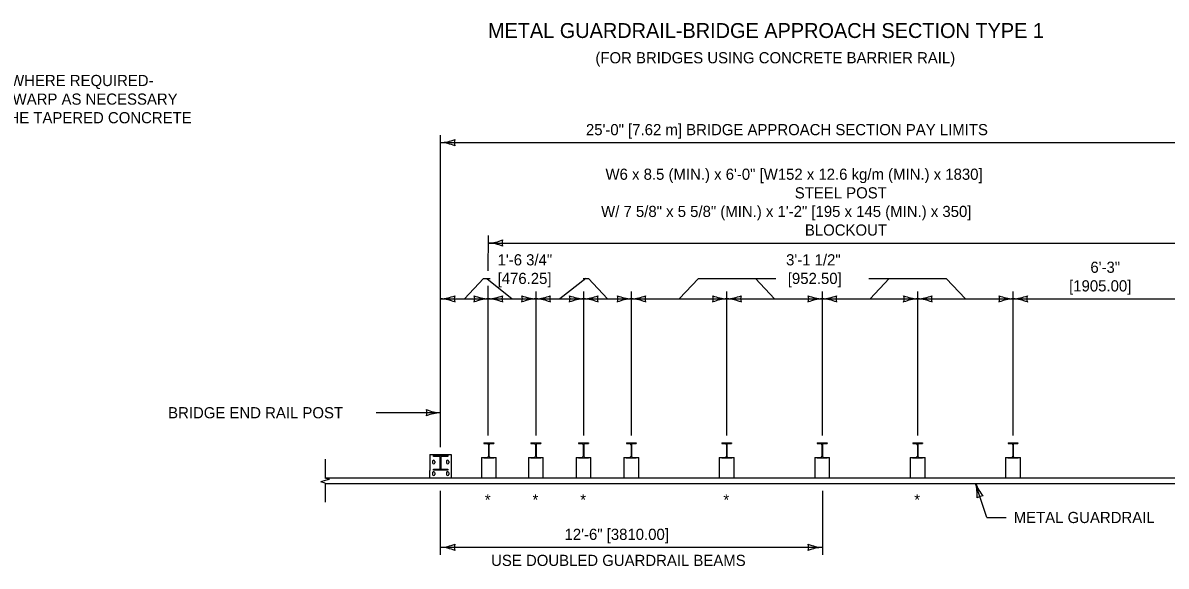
# Model space of a CAD drawing. Extents: x 49991.4 to 50021, y 49987.6 to 50011.4.
# Drawn here: x 50007.52 to 50013.67, y 49992.8 to 49995.72 of the extents above; entities that cross this region are included whole.
import ezdxf

# ---------------------------------------------------------------- set-up
doc = ezdxf.new("R2010")
doc.units = 0
for name, color, linetype in [('Level 1', 7, 'Continuous'), ('Level 2', 7, 'Continuous'), ('Level 3', 7, 'Continuous'), ('Level 6', 7, 'Continuous')]:
    doc.layers.add(name, color=color, linetype=linetype)

msp = doc.modelspace()

# ---------------------------------------------------------------- linework, layer by layer
at = {"layer": 'Level 1'}
for p, q in [((50010.0017, 49993.4645), (50010.0542, 49993.4645)), ((50010.0017, 49993.4645), (50010.0017, 49993.4616)), ((50010.0017, 49993.4616), (50010.0197, 49993.4616)), ((50010.0362, 49993.4616), (50010.0542, 49993.4616)), ((50010.0542, 49993.4645), (50010.0542, 49993.4616)), ((50010.2546, 49993.4645), (50010.3071, 49993.4645)), ((50010.2546, 49993.4645), (50010.2546, 49993.4616)), ((50010.2546, 49993.4616), (50010.2726, 49993.4616)), ((50010.2891, 49993.4616), (50010.3071, 49993.4616)), ((50010.3071, 49993.4645), (50010.3071, 49993.4616)), ((50010.5112, 49993.4645), (50010.5637, 49993.4645)), ((50010.5112, 49993.4645), (50010.5112, 49993.4616)), ((50010.5112, 49993.4616), (50010.5292, 49993.4616)), ((50010.5457, 49993.4616), (50010.5637, 49993.4616)), ((50010.5637, 49993.4645), (50010.5637, 49993.4616)), ((50010.7678, 49993.4645), (50010.8203, 49993.4645)), ((50010.7678, 49993.4645), (50010.7678, 49993.4616)), ((50010.7678, 49993.4616), (50010.7858, 49993.4616)), ((50010.8023, 49993.4616), (50010.8203, 49993.4616)), ((50010.8203, 49993.4645), (50010.8203, 49993.4616)), ((50011.281, 49993.4645), (50011.3335, 49993.4645)), ((50011.281, 49993.4645), (50011.281, 49993.4616)), ((50011.281, 49993.4616), (50011.299, 49993.4616)), ((50011.3155, 49993.4616), (50011.3335, 49993.4616)), ((50011.3335, 49993.4645), (50011.3335, 49993.4616)), ((50011.7942, 49993.4645), (50011.8467, 49993.4645)), ((50011.7942, 49993.4645), (50011.7942, 49993.4616)), ((50011.7942, 49993.4616), (50011.8122, 49993.4616)), ((50011.8287, 49993.4616), (50011.8467, 49993.4616)), ((50011.8467, 49993.4645), (50011.8467, 49993.4616)), ((50012.3074, 49993.4645), (50012.3599, 49993.4645)), ((50012.3074, 49993.4645), (50012.3074, 49993.4616)), ((50012.3074, 49993.4616), (50012.3254, 49993.4616)), ((50012.3419, 49993.4616), (50012.3599, 49993.4616)), ((50012.3599, 49993.4645), (50012.3599, 49993.4616)), ((50012.8206, 49993.4645), (50012.8731, 49993.4645)), ((50012.8206, 49993.4645), (50012.8206, 49993.4616)), ((50012.8206, 49993.4616), (50012.8386, 49993.4616)), ((50012.8551, 49993.4616), (50012.8731, 49993.4616)), ((50012.8731, 49993.4645), (50012.8731, 49993.4616)), ((50009.7114, 49993.402), (50009.8264, 49993.402)), ((50009.7114, 49993.402), (50009.7114, 49993.3163)), ((50009.8264, 49993.402), (50009.8264, 49993.3163)), ((50010.0268, 49993.4545), (50010.0268, 49993.3944)), ((50010.0291, 49993.4545), (50010.0291, 49993.3944)), ((50010.2797, 49993.4545), (50010.2797, 49993.3944)), ((50010.282, 49993.4545), (50010.282, 49993.3944)), ((50010.5363, 49993.4545), (50010.5363, 49993.3944)), ((50010.5386, 49993.4545), (50010.5386, 49993.3944)), ((50010.7929, 49993.4545), (50010.7929, 49993.3944)), ((50010.7952, 49993.4545), (50010.7952, 49993.3944)), ((50011.3061, 49993.4545), (50011.3061, 49993.3944)), ((50011.3084, 49993.4545), (50011.3084, 49993.3944)), ((50011.8193, 49993.4545), (50011.8193, 49993.3944)), ((50011.8216, 49993.4545), (50011.8216, 49993.3944)), ((50012.3325, 49993.4545), (50012.3325, 49993.3944)), ((50012.3348, 49993.4545), (50012.3348, 49993.3944)), ((50012.8457, 49993.4545), (50012.8457, 49993.3944)), ((50012.848, 49993.4545), (50012.848, 49993.3944)), ((50009.7249, 49993.3657), (50009.7249, 49993.3584)), ((50009.7307, 49993.397), (50009.8071, 49993.397)), ((50009.7307, 49993.3924), (50009.7307, 49993.397)), ((50009.7623, 49993.3924), (50009.7307, 49993.3924)), ((50009.7376, 49993.3657), (50009.7376, 49993.3584)), ((50009.7672, 49993.3281), (50009.7672, 49993.3875)), ((50009.7705, 49993.3875), (50009.7705, 49993.3281)), ((50009.8071, 49993.3924), (50009.7754, 49993.3924)), ((50009.8, 49993.3657), (50009.8, 49993.3584)), ((50009.8071, 49993.397), (50009.8071, 49993.3924)), ((50009.8128, 49993.3657), (50009.8128, 49993.3584)), ((50009.9879, 49993.3873), (50009.9879, 49993.277)), ((50009.9879, 49993.3873), (50010.001, 49993.3873)), ((50010.001, 49993.3844), (50010.001, 49993.3873)), ((50010.001, 49993.3844), (50010.0549, 49993.3844)), ((50010.0017, 49993.3844), (50010.0017, 49993.3873)), ((50010.0017, 49993.3873), (50010.0197, 49993.3873)), ((50010.0362, 49993.3873), (50010.0542, 49993.3873)), ((50010.0542, 49993.3844), (50010.0542, 49993.3873)), ((50010.0549, 49993.3844), (50010.0549, 49993.3873)), ((50010.0549, 49993.3873), (50010.068, 49993.3873)), ((50010.068, 49993.277), (50010.068, 49993.3873)), ((50010.2408, 49993.3873), (50010.2408, 49993.277)), ((50010.2408, 49993.3873), (50010.2539, 49993.3873)), ((50010.2539, 49993.3844), (50010.2539, 49993.3873)), ((50010.2539, 49993.3844), (50010.3078, 49993.3844)), ((50010.2546, 49993.3844), (50010.2546, 49993.3873)), ((50010.2546, 49993.3873), (50010.2726, 49993.3873)), ((50010.2891, 49993.3873), (50010.3071, 49993.3873)), ((50010.3071, 49993.3844), (50010.3071, 49993.3873)), ((50010.3078, 49993.3844), (50010.3078, 49993.3873)), ((50010.3078, 49993.3873), (50010.3209, 49993.3873)), ((50010.3209, 49993.277), (50010.3209, 49993.3873)), ((50010.4974, 49993.3873), (50010.4974, 49993.277)), ((50010.4974, 49993.3873), (50010.5105, 49993.3873)), ((50010.5105, 49993.3844), (50010.5105, 49993.3873)), ((50010.5105, 49993.3844), (50010.5644, 49993.3844)), ((50010.5112, 49993.3844), (50010.5112, 49993.3873)), ((50010.5112, 49993.3873), (50010.5292, 49993.3873)), ((50010.5457, 49993.3873), (50010.5637, 49993.3873)), ((50010.5637, 49993.3844), (50010.5637, 49993.3873)), ((50010.5644, 49993.3844), (50010.5644, 49993.3873)), ((50010.5644, 49993.3873), (50010.5775, 49993.3873)), ((50010.5775, 49993.277), (50010.5775, 49993.3873)), ((50010.754, 49993.3873), (50010.754, 49993.277)), ((50010.754, 49993.3873), (50010.7671, 49993.3873)), ((50010.7671, 49993.3844), (50010.7671, 49993.3873)), ((50010.7671, 49993.3844), (50010.821, 49993.3844)), ((50010.7678, 49993.3844), (50010.7678, 49993.3873)), ((50010.7678, 49993.3873), (50010.7858, 49993.3873)), ((50010.8023, 49993.3873), (50010.8203, 49993.3873)), ((50010.8203, 49993.3844), (50010.8203, 49993.3873)), ((50010.821, 49993.3844), (50010.821, 49993.3873)), ((50010.821, 49993.3873), (50010.8341, 49993.3873)), ((50010.8341, 49993.277), (50010.8341, 49993.3873)), ((50011.2672, 49993.3873), (50011.2672, 49993.277)), ((50011.2672, 49993.3873), (50011.2803, 49993.3873)), ((50011.2803, 49993.3844), (50011.2803, 49993.3873)), ((50011.2803, 49993.3844), (50011.3342, 49993.3844)), ((50011.281, 49993.3844), (50011.281, 49993.3873)), ((50011.281, 49993.3873), (50011.299, 49993.3873)), ((50011.3155, 49993.3873), (50011.3335, 49993.3873)), ((50011.3335, 49993.3844), (50011.3335, 49993.3873)), ((50011.3342, 49993.3844), (50011.3342, 49993.3873)), ((50011.3342, 49993.3873), (50011.3473, 49993.3873)), ((50011.3473, 49993.277), (50011.3473, 49993.3873)), ((50011.7804, 49993.3873), (50011.7804, 49993.277)), ((50011.7804, 49993.3873), (50011.7935, 49993.3873)), ((50011.7935, 49993.3844), (50011.7935, 49993.3873)), ((50011.7935, 49993.3844), (50011.8474, 49993.3844)), ((50011.7942, 49993.3844), (50011.7942, 49993.3873)), ((50011.7942, 49993.3873), (50011.8122, 49993.3873)), ((50011.8287, 49993.3873), (50011.8467, 49993.3873)), ((50011.8467, 49993.3844), (50011.8467, 49993.3873)), ((50011.8474, 49993.3844), (50011.8474, 49993.3873)), ((50011.8474, 49993.3873), (50011.8605, 49993.3873)), ((50011.8605, 49993.277), (50011.8605, 49993.3873)), ((50012.2936, 49993.3873), (50012.2936, 49993.277)), ((50012.2936, 49993.3873), (50012.3067, 49993.3873)), ((50012.3067, 49993.3844), (50012.3067, 49993.3873)), ((50012.3067, 49993.3844), (50012.3606, 49993.3844)), ((50012.3074, 49993.3844), (50012.3074, 49993.3873)), ((50012.3074, 49993.3873), (50012.3254, 49993.3873)), ((50012.3419, 49993.3873), (50012.3599, 49993.3873)), ((50012.3599, 49993.3844), (50012.3599, 49993.3873)), ((50012.3606, 49993.3844), (50012.3606, 49993.3873)), ((50012.3606, 49993.3873), (50012.3737, 49993.3873)), ((50012.3737, 49993.277), (50012.3737, 49993.3873)), ((50012.8068, 49993.3873), (50012.8068, 49993.277)), ((50012.8068, 49993.3873), (50012.8199, 49993.3873)), ((50012.8199, 49993.3844), (50012.8199, 49993.3873)), ((50012.8199, 49993.3844), (50012.8738, 49993.3844)), ((50012.8206, 49993.3844), (50012.8206, 49993.3873)), ((50012.8206, 49993.3873), (50012.8386, 49993.3873)), ((50012.8551, 49993.3873), (50012.8731, 49993.3873)), ((50012.8731, 49993.3844), (50012.8731, 49993.3873)), ((50012.8738, 49993.3844), (50012.8738, 49993.3873)), ((50012.8738, 49993.3873), (50012.8869, 49993.3873)), ((50012.8869, 49993.277), (50012.8869, 49993.3873)), ((50009.1482, 49993.277), (50014.1642, 49993.277)), ((50009.7114, 49993.277), (50009.7114, 49993.3163)), ((50009.7114, 49993.277), (50009.8264, 49993.277)), ((50009.7249, 49993.3032), (50009.7249, 49993.2959)), ((50009.7308, 49993.3183), (50009.7308, 49993.3229)), ((50009.7308, 49993.3229), (50009.7624, 49993.3229)), ((50009.8072, 49993.3183), (50009.7308, 49993.3183)), ((50009.7376, 49993.3032), (50009.7376, 49993.2959)), ((50009.7754, 49993.3229), (50009.8072, 49993.3229)), ((50009.7999, 49993.3032), (50009.7999, 49993.2959)), ((50009.8072, 49993.3229), (50009.8072, 49993.3183)), ((50009.8126, 49993.3032), (50009.8126, 49993.2959)), ((50009.8264, 49993.3163), (50009.8264, 49993.277)), ((50009.1482, 49993.247), (50014.1642, 49993.247))]:
    msp.add_line(p, q, dxfattribs=at)
for centre, radius, start, end in [((50010.0197, 49993.4545), 0.00714, 0, 90), ((50010.0362, 49993.4545), 0.00714, 90, 180), ((50010.2726, 49993.4545), 0.00714, 0, 90), ((50010.2891, 49993.4545), 0.00714, 90, 180), ((50010.5292, 49993.4545), 0.00714, 0, 90), ((50010.5457, 49993.4545), 0.00714, 90, 180), ((50010.7858, 49993.4545), 0.00714, 0, 90), ((50010.8023, 49993.4545), 0.00714, 90, 180), ((50011.299, 49993.4545), 0.00714, 0, 90), ((50011.3155, 49993.4545), 0.00714, 90, 180), ((50011.8122, 49993.4545), 0.00714, 0, 90), ((50011.8287, 49993.4545), 0.00714, 90, 180), ((50012.3254, 49993.4545), 0.00714, 0, 90), ((50012.3419, 49993.4545), 0.00714, 90, 180), ((50012.8386, 49993.4545), 0.00714, 0, 90), ((50012.8551, 49993.4545), 0.00714, 90, 180), ((50009.7313, 49993.3657), 0.00635, 359.99369, 180.03756), ((50009.7313, 49993.3584), 0.00635, 180.00006, 359.9937), ((50009.7623, 49993.3875), 0.00489, 0, 90), ((50009.7754, 49993.3875), 0.00489, 90, 180), ((50009.8063, 49993.3657), 0.00635, 359.99369, 180.03756), ((50009.8063, 49993.3584), 0.00635, 180.00006, 359.9937), ((50010.0197, 49993.3944), 0.00714, 270, 0), ((50010.0362, 49993.3944), 0.00714, 180, 270), ((50010.2726, 49993.3944), 0.00714, 270, 0), ((50010.2891, 49993.3944), 0.00714, 180, 270), ((50010.5292, 49993.3944), 0.00714, 270, 0), ((50010.5457, 49993.3944), 0.00714, 180, 270), ((50010.7858, 49993.3944), 0.00714, 270, 0), ((50010.8023, 49993.3944), 0.00714, 180, 270), ((50011.299, 49993.3944), 0.00714, 270, 0), ((50011.3155, 49993.3944), 0.00714, 180, 270), ((50011.8122, 49993.3944), 0.00714, 270, 0), ((50011.8287, 49993.3944), 0.00714, 180, 270), ((50012.3254, 49993.3944), 0.00714, 270, 0), ((50012.3419, 49993.3944), 0.00714, 180, 270), ((50012.8386, 49993.3944), 0.00714, 270, 0), ((50012.8551, 49993.3944), 0.00714, 180, 270), ((50009.7313, 49993.3032), 0.00635, 359.99369, 180.03756), ((50009.7313, 49993.2959), 0.00635, 180.00006, 359.9937), ((50009.7627, 49993.3274), 0.00455, 266.76442, 8.43425), ((50009.7755, 49993.3279), 0.00499, 177.45438, 269.51567), ((50009.8063, 49993.3032), 0.00635, 359.99369, 180.03756), ((50009.8063, 49993.2959), 0.00635, 180.00006, 359.9937)]:
    msp.add_arc(centre, radius, start, end, dxfattribs=at)
at = {"layer": 'Level 3'}
for p, q in [((50009.7689, 49993.442), (50009.7689, 49995.1188)), ((50009.7689, 49995.0788), (50014.8318, 49995.0788)), ((50010.0255, 49994.3891), (50010.0257, 49994.5791)), ((50010.0257, 49994.5391), (50013.8745, 49994.5391)), ((50010, 49994.3491), (50009.8966, 49994.2391)), ((50010, 49994.3491), (50010.0354, 49994.3491)), ((50010.0177, 49994.3491), (50010.1532, 49994.2391)), ((50010.5493, 49994.3491), (50010.4104, 49994.2391)), ((50010.535, 49994.3491), (50010.5636, 49994.3491)), ((50010.5636, 49994.3491), (50010.667, 49994.2391)), ((50011.1553, 49994.3491), (50011.0519, 49994.2391)), ((50011.1553, 49994.3491), (50011.5721, 49994.3491)), ((50011.4617, 49994.3491), (50011.5651, 49994.2391)), ((50012.0716, 49994.3491), (50012.4881, 49994.3491)), ((50012.1817, 49994.3491), (50012.0783, 49994.2391)), ((50012.4881, 49994.3491), (50012.5915, 49994.2391)), ((50010.0255, 49993.5045), (50010.0255, 49994.3091)), ((50010.2821, 49993.5045), (50010.2821, 49994.2791)), ((50010.5387, 49993.5045), (50010.5387, 49994.2791)), ((50010.7953, 49993.5045), (50010.7953, 49994.2791)), ((50011.3085, 49993.5045), (50011.3085, 49994.2791)), ((50011.8217, 49993.5045), (50011.8217, 49994.2791)), ((50012.3349, 49993.5045), (50012.3349, 49994.2791)), ((50012.8481, 49993.5045), (50012.8481, 49994.2791)), ((50009.7689, 49994.2391), (50013.8745, 49994.2391)), ((50009.7689, 49993.6271), (50009.4231, 49993.6271)), ((50012.7056, 49993.0641), (50012.6461, 49993.247)), ((50009.7689, 49992.8635), (50009.7689, 49993.207)), ((50011.8219, 49993.207), (50011.8219, 49992.8635)), ((50012.7056, 49993.0641), (50012.8107, 49993.0641)), ((50011.8219, 49992.9035), (50009.7689, 49992.9035))]:
    msp.add_line(p, q, dxfattribs=at)
for centre, radius, start, end in [((50009.7574, 49995.3115), 0.233, 272.82731, 292.07716), ((50009.7598, 49994.8566), 0.2223, 67.45601, 87.63952), ((50009.8971, 49995.0788), 0.0548, 162.13882, 197.86118), ((50010.0142, 49994.7718), 0.233, 272.82731, 292.07716), ((50010.0165, 49994.317), 0.2223, 67.45601, 87.63952), ((50010.1539, 49994.5391), 0.0548, 162.13882, 197.86118), ((50009.7574, 49994.4718), 0.233, 272.82731, 292.07716), ((50009.7598, 49994.017), 0.2223, 67.45601, 87.63952), ((50009.8971, 49994.2391), 0.0548, 162.13882, 197.86118), ((50010.0347, 49994.4612), 0.2223, 247.45601, 267.63952), ((50009.8973, 49994.2391), 0.0548, 342.13882, 17.86118), ((50010.037, 49994.0064), 0.233, 92.82731, 112.07716), ((50010.014, 49994.4718), 0.233, 272.82731, 292.07716), ((50010.0164, 49994.017), 0.2223, 67.45601, 87.63952), ((50010.1537, 49994.2391), 0.0548, 162.13882, 197.86118), ((50010.2913, 49994.4612), 0.2223, 247.45601, 267.63952), ((50010.1539, 49994.2391), 0.0548, 342.13882, 17.86118), ((50010.2936, 49994.0064), 0.233, 92.82731, 112.07716), ((50010.2706, 49994.4718), 0.233, 272.82731, 292.07716), ((50010.273, 49994.017), 0.2223, 67.45601, 87.63952), ((50010.4103, 49994.2391), 0.0548, 162.13882, 197.86118), ((50010.5479, 49994.4612), 0.2223, 247.45601, 267.63952), ((50010.4105, 49994.2391), 0.0548, 342.13882, 17.86118), ((50010.5502, 49994.0064), 0.233, 92.82731, 112.07716), ((50010.5272, 49994.4718), 0.233, 272.82731, 292.07716), ((50010.5296, 49994.017), 0.2223, 67.45601, 87.63952), ((50010.6669, 49994.2391), 0.0548, 162.13882, 197.86118), ((50010.8045, 49994.4612), 0.2223, 247.45601, 267.63952), ((50010.6671, 49994.2391), 0.0548, 342.13882, 17.86118), ((50010.8068, 49994.0064), 0.233, 92.82731, 112.07716), ((50010.7838, 49994.4718), 0.233, 272.82731, 292.07716), ((50010.7862, 49994.017), 0.2223, 67.45601, 87.63952), ((50010.9235, 49994.2391), 0.0548, 162.13882, 197.86118), ((50011.3177, 49994.4612), 0.2223, 247.45601, 267.63952), ((50011.1803, 49994.2391), 0.0548, 342.13882, 17.86118), ((50011.32, 49994.0064), 0.233, 92.82731, 112.07716), ((50011.297, 49994.4718), 0.233, 272.82731, 292.07716), ((50011.2994, 49994.017), 0.2223, 67.45601, 87.63952), ((50011.4367, 49994.2391), 0.0548, 162.13882, 197.86118), ((50011.8309, 49994.4612), 0.2223, 247.45601, 267.63952), ((50011.6935, 49994.2391), 0.0548, 342.13882, 17.86118), ((50011.8332, 49994.0064), 0.233, 92.82731, 112.07716), ((50011.8102, 49994.4718), 0.233, 272.82731, 292.07716), ((50011.8126, 49994.017), 0.2223, 67.45601, 87.63952), ((50011.9499, 49994.2391), 0.0548, 162.13882, 197.86118), ((50012.3441, 49994.4612), 0.2223, 247.45601, 267.63952), ((50012.2067, 49994.2391), 0.0548, 342.13882, 17.86118), ((50012.3464, 49994.0064), 0.233, 92.82731, 112.07716), ((50012.3234, 49994.4718), 0.233, 272.82731, 292.07716), ((50012.3258, 49994.017), 0.2223, 67.45601, 87.63952), ((50012.4631, 49994.2391), 0.0548, 162.13882, 197.86118), ((50012.8573, 49994.4612), 0.2223, 247.45601, 267.63952), ((50012.7199, 49994.2391), 0.0548, 342.13882, 17.86118), ((50012.8596, 49994.0064), 0.233, 92.82731, 112.07716), ((50012.8366, 49994.4718), 0.233, 272.82731, 292.07716), ((50012.839, 49994.017), 0.2223, 67.45601, 87.63952), ((50012.9763, 49994.2391), 0.0548, 162.13882, 197.86118), ((50009.7781, 49993.8492), 0.2223, 247.45601, 267.63952), ((50009.6407, 49993.6271), 0.0548, 342.13882, 17.86118), ((50009.7804, 49993.3944), 0.233, 92.82731, 112.07716), ((50012.432, 49993.187), 0.2223, 355.47646, 15.65997), ((50012.8639, 49993.3299), 0.233, 200.84776, 220.09761), ((50012.6858, 49993.1251), 0.0548, 90.15927, 125.88163), ((50009.7574, 49993.1362), 0.233, 272.82731, 292.07716), ((50009.8971, 49992.9035), 0.0548, 162.13882, 197.86118), ((50011.8311, 49993.1256), 0.2223, 247.45601, 267.63952), ((50011.6937, 49992.9035), 0.0548, 342.13882, 17.86118), ((50009.7598, 49992.6814), 0.2223, 67.45601, 87.63952), ((50011.8334, 49992.6708), 0.233, 92.82731, 112.07716)]:
    msp.add_arc(centre, radius, start, end, dxfattribs=at)
at = {"layer": 'Level 6'}
for p, q in [((50009.1482, 49993.377), (50009.1482, 49993.275)), ((50009.1482, 49993.2621), (50009.1253, 49993.2556)), ((50009.1482, 49993.2492), (50009.1253, 49993.2556)), ((50009.1711, 49993.2686), (50009.1482, 49993.275)), ((50009.1711, 49993.2686), (50009.1482, 49993.2621)), ((50009.1482, 49993.2492), (50009.1482, 49993.147))]:
    msp.add_line(p, q, dxfattribs=at)

# ---------------------------------------------------------------- texts
at = {"layer": 'Level 2'}
for s, height, p in [('METAL GUARDRAIL-BRIDGE APPROACH SECTION TYPE 1', 0.08, (50010.0234, 49995.6414)), ('(FOR BRIDGES USING CONCRETE BARRIER RAIL)', 0.06, (50010.6013, 49995.5052)), ('STD. CONC. CURB (WHERE REQUIRED-', 0.06, (50006.6917, 49995.3829)), ('SEE ROAD PLANS) (WARP AS NECESSARY', 0.06, (50006.6917, 49995.2829)), ('TO MEET END OF THE TAPERED CONCRETE ', 0.06, (50006.6917, 49995.1829)), ('25\'-0" [7.62 m] BRIDGE APPROACH SECTION PAY LIMITS', 0.06, (50010.5504, 49995.1188)), ('W6 x 8.5 (MIN.) x 6\'-0" [W152 x 12.6 kg/m (MIN.) x 1830]', 0.06, (50010.6556, 49994.8791)), ('STEEL POST', 0.06, (50011.6734, 49994.7791)), ('W/ 7 5/8" x 5 5/8" (MIN.) x 1\'-2" [195 x 145 (MIN.) x 350]', 0.06, (50010.632, 49994.6791)), ('BLOCKOUT', 0.06, (50011.7278, 49994.5791)), ('1\'-6 3/4"', 0.06, (50010.0754, 49994.4191)), ('3\'-1 1/2"', 0.06, (50011.6266, 49994.4191)), ('6\'-3"', 0.06, (50013.263, 49994.3791)), ('[476.25]', 0.06, (50010.0754, 49994.3191)), ('[952.50]', 0.06, (50011.6359, 49994.3191)), ('[1905.00]', 0.06, (50013.1486, 49994.2791)), ('BRIDGE END RAIL POST', 0.06, (50008.3036, 49993.5971)), ('*', 0.06, (50010.0065, 49993.1291)), ('*', 0.06, (50010.2631, 49993.1291)), ('*', 0.06, (50010.5197, 49993.1291)), ('*', 0.06, (50011.2895, 49993.1291)), ('*', 0.06, (50012.3159, 49993.1291)), ('METAL GUARDRAIL', 0.06, (50012.8507, 49993.0341)), ('12\'-6" [3810.00]', 0.06, (50010.4354, 49992.9435)), ('USE DOUBLED GUARDRAIL BEAMS', 0.06, (50010.0406, 49992.8035))]:
    msp.add_text(s, height=height, dxfattribs=at).set_placement(p)

doc.saveas('drawing.dxf')
